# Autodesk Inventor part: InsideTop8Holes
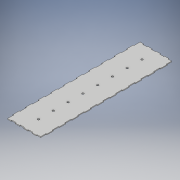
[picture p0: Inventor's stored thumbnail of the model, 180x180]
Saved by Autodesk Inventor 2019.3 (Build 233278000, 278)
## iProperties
Created: 2020-02
Part Number: InsideTop8Holes
Material: Generic
Document SubType Name: Modeling
Designer: KrystynWikoff
Density: 1 g/cm^3
Appearance: Default
Author: KrystynWikoff
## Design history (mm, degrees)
sketch "Sketch1"
  geometry: L1 (0, 0)-(101.6, 0); L2 (101.6, 0)-(101.6, -398.424); L3 (101.6, -398.424)-(0, -398.424); L4 (0, -398.424)-(0, 0)
  constraints: 8 end point, 2 parallel, 1 horizontal, 1 perpendicular
  dimensions: "d0" = 398.4244 distance of L3.end L1.start; "d1" = 101.6 distance of L1.start L1.end
extrude "Extrusion1" new body sketch "Sketch1" distance "d2" = 2.3622; taper "d3" = 0 deg
sketch "Sketch2" dims "d18" = 25.4
  geometry: L1 (-101.6, 0)-(-99.238, 0); L2 (-99.238, 0)-(-99.238, 18.237); L3 (-99.238, 18.237)-(-101.6, 18.237); L4 (-101.6, 18.237)-(-101.6, 0); L5 (-101.6, 0)-(0, 0) reference; L6 (-101.6, 398.424)-(-101.6, 0) reference; L7 (-101.6, 398.424)-(-99.238, 398.424); L8 (-99.238, 398.424)-(-99.238, 380.187); L9 (-99.238, 380.187)-(-101.6, 380.187); L10 (-101.6, 380.187)-(-101.6, 398.424); L11 (-101.6, 37.287)-(-99.238, 37.287); L12 (-99.238, 37.287)-(-99.238, 56.337); L13 (-99.238, 56.337)-(-101.6, 56.337); L14 (-101.6, 56.337)-(-101.6, 37.287); L15 (-99.238, 94.437)-(-101.6, 94.437); L16 (-99.238, 75.387)-(-99.238, 94.437); L17 (-101.6, 94.437)-(-101.6, 75.387); L18 (-101.6, 75.387)-(-99.238, 75.387); L19 (-99.238, 132.537)-(-101.6, 132.537); L20 (-99.238, 113.487)-(-99.238, 132.537); L21 (-101.6, 132.537)-(-101.6, 113.487); L22 (-101.6, 113.487)-(-99.238, 113.487); L23 (-99.238, 170.637)-(-101.6, 170.637); L24 (-99.238, 151.587)-(-99.238, 170.637); L25 (-101.6, 170.637)-(-101.6, 151.587); L26 (-101.6, 151.587)-(-99.238, 151.587); L27 (-99.238, 208.737)-(-101.6, 208.737); L28 (-99.238, 189.687)-(-99.238, 208.737); L29 (-101.6, 208.737)-(-101.6, 189.687); L30 (-101.6, 189.687)-(-99.238, 189.687); L31 (-99.238, 246.837)-(-101.6, 246.837); L32 (-99.238, 227.787)-(-99.238, 246.837); L33 (-101.6, 246.837)-(-101.6, 227.787); L34 (-101.6, 227.787)-(-99.238, 227.787); L35 (-99.238, 284.937)-(-101.6, 284.937); L36 (-99.238, 265.887)-(-99.238, 284.937); L37 (-101.6, 284.937)-(-101.6, 265.887); L38 (-101.6, 265.887)-(-99.238, 265.887); L39 (-99.238, 323.037)-(-101.6, 323.037); L40 (-99.238, 303.987)-(-99.238, 323.037); L41 (-101.6, 323.037)-(-101.6, 303.987); L42 (-101.6, 303.987)-(-99.238, 303.987); L43 (-99.238, 361.137)-(-101.6, 361.137); L44 (-99.238, 342.087)-(-99.238, 361.137); L45 (-101.6, 361.137)-(-101.6, 342.087); L46 (-101.6, 342.087)-(-99.238, 342.087)
  constraints: 88 end point, 6 parallel, 3 horizontal, 3 perpendicular, 1 point on line, 1 vertical, 64 other
  dimensions: "d4" = 0 distance between parallel lines of L1 L5; "d5" = 18.2372 distance of L1.end L2.end; "d6" = 2.3622 distance of L1.start L1.end; "d7" = 0 distance between parallel lines of L6 L4; "d8" = 2.3622 distance of L8.end L9.end; "d9" = 18.2372 distance of L7.end L8.end; "d10" = 19.05 distance of L11.end L12.end; "d11" = 19.05 distance between parallel lines of L11 L3; "d12" = 2.3622 distance of L11.start L11.end; "d15" = 38.1 distance of L12.end L15.start
extrude "Extrusion2" cut sketch "Sketch2" distance "d20" = 2.3622; taper "d21" = 0 deg
sketch "Sketch3" dims "d30" = 25.4, "d41" = 25.4
  geometry: L1 (0, 0)-(-99.238, 0) reference; L2 (-76.2, 0)-(-88.9, 0); L3 (-88.9, 0)-(-88.9, 2.362); L4 (-88.9, 2.362)-(-76.2, 2.362); L5 (-76.2, 2.362)-(-76.2, 0); L6 (-101.6, 37.287)-(-101.6, 18.237) reference; L7 (-50.8, 0)-(-63.5, 0); L8 (-63.5, 0)-(-63.5, 2.362); L9 (-63.5, 2.362)-(-50.8, 2.362); L10 (-50.8, 2.362)-(-50.8, 0); L11 (-25.4, 0)-(-38.1, 0); L12 (-38.1, 0)-(-38.1, 2.362); L13 (-38.1, 2.362)-(-25.4, 2.362); L14 (-25.4, 2.362)-(-25.4, 0); L15 (0, 0)-(-12.7, 0); L16 (-12.7, 0)-(-12.7, 2.362); L17 (-12.7, 2.362)-(0, 2.362); L18 (0, 2.362)-(0, 0); L19 (-88.9, 398.424)-(-76.2, 398.424); L20 (-76.2, 398.424)-(-76.2, 396.062); L21 (-76.2, 396.062)-(-88.9, 396.062); L22 (-88.9, 396.062)-(-88.9, 398.424); L23 (0, 398.424)-(-99.238, 398.424) reference; L24 (-101.6, 380.187)-(-101.6, 361.137) reference; L25 (-50.8, 398.424)-(-50.8, 396.062); L26 (-50.8, 396.062)-(-63.5, 396.062); L27 (-63.5, 396.062)-(-63.5, 398.424); L28 (-63.5, 398.424)-(-50.8, 398.424); L29 (-25.4, 398.424)-(-25.4, 396.062); L30 (-25.4, 396.062)-(-38.1, 396.062); L31 (-38.1, 396.062)-(-38.1, 398.424); L32 (-38.1, 398.424)-(-25.4, 398.424); L33 (0, 398.424)-(0, 396.062); L34 (0, 396.062)-(-12.7, 396.062); L35 (-12.7, 396.062)-(-12.7, 398.424); L36 (-12.7, 398.424)-(0, 398.424)
  constraints: 64 end point, 4 horizontal, 4 parallel, 2 perpendicular, 1 point on line, 48 other
  dimensions: "d22" = 2.3622 distance of L4.end L2.start; "d23" = 12.7 distance between parallel lines of L6 L3; "d24" = 12.7 distance of L3.end L4.end; "d27" = 25.4 distance of L2.start L7.start; "d32" = 2.3622 distance of L19.end L20.end; "d33" = 0 distance between parallel lines of L23 L19; "d34" = 12.7 distance between parallel lines of L24 L22; "d35" = 12.7 distance of L20.end L21.end; "d38" = 25.4 distance of L20.end L25.end
extrude "Extrusion3" cut sketch "Sketch3" distance "d43" = 2.3622; taper "d44" = 0 deg
sketch "Sketch4" dims "d53" = 25.4
  geometry: L1 (-101.6, 37.287)-(-101.6, 18.237) reference; L2 (-50.8, 0)-(-38.1, 0) reference; C1 r 3.01 at (-50.8, 44.45); C2 r 3.01 at (-50.8, 88.9); C3 r 3.01 at (-50.8, 133.35); C4 r 3.01 at (-50.8, 177.8); C5 r 3.01 at (-50.8, 222.25); C6 r 3.01 at (-50.8, 266.7); C7 r 3.01 at (-50.8, 311.15); C8 r 3.01 at (-50.8, 355.6); 1 further point
  constraints: 8 centre point, 1 vertical, 14 other
  dimensions: "d45" = 6.0198 diameter of C1; "d46" = 50.8 distance from line of C1.centre L1; "d47" = 44.45 distance from line of L2 C1.centre; "d50" = 44.45 distance of C1.centre C2.centre
extrude "Extrusion4" cut sketch "Sketch4" distance "d55" = 25.4; taper "d56" = 0 deg
sketch "Sketch5" dims "d67" = 25.4
  geometry: L1 (0, 0)-(-2.362, 0); L2 (-2.362, 0)-(-2.362, 18.237); L3 (-2.362, 18.237)-(0, 18.237); L4 (0, 18.237)-(0, 0); L5 (0, 396.062)-(0, 2.362) reference; L6 (0, 37.287)-(-2.362, 37.287); L7 (-2.362, 37.287)-(-2.362, 56.337); L8 (-2.362, 56.337)-(0, 56.337); L9 (0, 56.337)-(0, 37.287); L10 (0, 75.387)-(-2.362, 75.387); L11 (-2.362, 75.387)-(-2.362, 94.437); L12 (-2.362, 94.437)-(0, 94.437); L13 (0, 94.437)-(0, 75.387); L14 (0, 113.487)-(-2.362, 113.487); L15 (-2.362, 113.487)-(-2.362, 132.537); L16 (-2.362, 132.537)-(0, 132.537); L17 (0, 132.537)-(0, 113.487); L18 (0, 151.587)-(-2.362, 151.587); L19 (-2.362, 151.587)-(-2.362, 170.637); L20 (-2.362, 170.637)-(0, 170.637); L21 (0, 170.637)-(0, 151.587); L22 (0, 189.687)-(-2.362, 189.687); L23 (-2.362, 189.687)-(-2.362, 208.737); L24 (-2.362, 208.737)-(0, 208.737); L25 (0, 208.737)-(0, 189.687); L26 (0, 227.787)-(-2.362, 227.787); L27 (-2.362, 227.787)-(-2.362, 246.837); L28 (-2.362, 246.837)-(0, 246.837); L29 (0, 246.837)-(0, 227.787); L30 (0, 265.887)-(-2.362, 265.887); L31 (-2.362, 265.887)-(-2.362, 284.937); L32 (-2.362, 284.937)-(0, 284.937); L33 (0, 284.937)-(0, 265.887); L34 (0, 303.987)-(-2.362, 303.987); L35 (-2.362, 303.987)-(-2.362, 323.037); L36 (-2.362, 323.037)-(0, 323.037); L37 (0, 323.037)-(0, 303.987); L38 (0, 342.087)-(-2.362, 342.087); L39 (-2.362, 342.087)-(-2.362, 361.137); L40 (-2.362, 361.137)-(0, 361.137); L41 (0, 361.137)-(0, 342.087); L42 (0, 380.187)-(-2.362, 380.187); L43 (-2.362, 380.187)-(-2.362, 398.424); L44 (-2.362, 398.424)-(0, 398.424); L45 (0, 398.424)-(0, 380.187); L46 (-12.7, 398.424)-(-25.4, 398.424) reference
  constraints: 88 end point, 6 parallel, 3 horizontal, 3 perpendicular, 2 point on line, 1 vertical, 64 other
  dimensions: "d57" = 18.2372 distance of L1.end L2.end; "d58" = 2.3622 distance of L2.end L3.end; "d59" = 19.05 distance between parallel lines of L3 L6; "d60" = 19.05 distance of L6.end L7.end; "d61" = 2.3622 distance of L6.start L6.end; "d64" = 38.1 distance of L6.start L10.start; "d69" = 2.3622 distance of L42.start L42.end; "d70" = 18.2372 distance between parallel lines of L46 L42; "d71" = 18.2372 distance of L42.end L43.end
extrude "Extrusion5" cut sketch "Sketch5" distance "d72" = 25.4; taper "d73" = 0 deg
body "Solid1"
